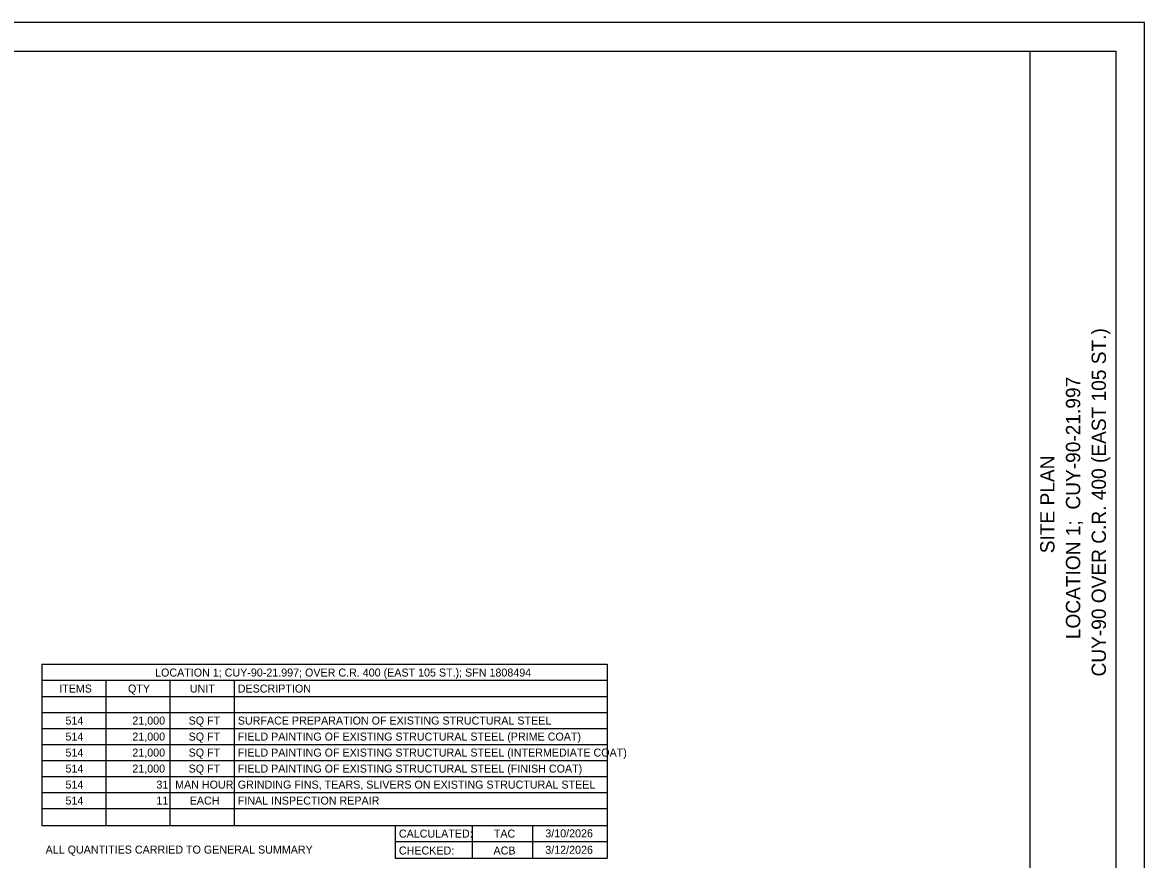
# Model space of a CAD drawing. Extents: x 0 to 34, y 0 to 22.
# Drawn here: x 14.38 to 34, y 7.36 to 22 of the extents above; entities that cross this region are included whole.
import ezdxf

# ---------------------------------------------------------------- set-up
doc = ezdxf.new("R2010")
doc.units = 0
for name, color, linetype in [('SH_Border', 7, 'Continuous'), ('SH_Cut_Line', 7, 'Continuous'), ('SH_Data', 7, 'Continuous'), ('SH_Text', 7, 'Continuous')]:
    doc.layers.add(name, color=color, linetype=linetype)

msp = doc.modelspace()

# ---------------------------------------------------------------- linework, layer by layer
at = {"layer": 'SH_Border'}
msp.add_line((32, 0.5), (32, 21.5), dxfattribs=at)
msp.add_lwpolyline([(1.5, 21.5), (33.5, 21.5), (33.5, 0.5), (1.5, 0.5)], close=True, dxfattribs=at)
at = {"layer": 'SH_Cut_Line'}
msp.add_lwpolyline([(0, 0), (34, 0), (34, 22), (0, 22)], close=True, dxfattribs=at)
at = {"layer": 'SH_Text'}
for p, q in [((14.718, 10.771), (24.601, 10.771)), ((14.718, 10.771), (14.718, 7.954)), ((24.601, 10.771), (24.601, 7.954)), ((14.718, 10.491), (24.601, 10.491)), ((15.838, 10.491), (15.838, 7.954)), ((16.958, 10.491), (16.958, 7.954)), ((18.078, 10.491), (18.078, 7.954)), ((14.718, 10.211), (24.601, 10.211)), ((14.718, 9.931), (24.601, 9.931)), ((14.718, 9.651), (24.601, 9.651)), ((14.718, 9.371), (24.601, 9.371)), ((14.718, 9.091), (24.601, 9.091)), ((14.718, 8.811), (24.601, 8.811)), ((14.718, 8.531), (24.601, 8.531)), ((14.718, 8.251), (24.601, 8.251)), ((14.718, 7.954), (24.601, 7.954)), ((20.895, 7.954), (24.601, 7.954)), ((20.895, 7.954), (20.895, 7.378)), ((22.245, 7.954), (22.245, 7.378)), ((23.3, 7.954), (23.3, 7.378)), ((24.601, 7.954), (24.601, 7.378)), ((20.895, 7.674), (24.601, 7.674)), ((20.895, 7.378), (24.601, 7.378))]:
    msp.add_line(p, q, dxfattribs=at)

# ---------------------------------------------------------------- texts
at = {"layer": 'SH_Data'}
for s, p in [('CUY-90 OVER C.R. 400 (EAST 105 ST.)', (33.325, 10.558)), ('LOCATION 1;  CUY-90-21.997', (32.875, 11.211)), ('SITE PLAN', (32.425, 12.714))]:
    msp.add_text(s, height=0.25, rotation=90, dxfattribs=at).set_placement(p)
at = {"layer": 'SH_Text'}
for s, p in [('LOCATION 1; CUY-90-21.997; OVER C.R. 400 (EAST 105 ST.); SFN 1808494', (16.698, 10.557)), ('ITEMS', (15.021, 10.277)), ('QTY', (16.225, 10.277)), ('UNIT', (17.306, 10.277)), ('DESCRIPTION', (18.144, 10.277)), ('514', (15.131, 9.717)), ('      21,000', (15.988, 9.717)), ('SQ FT', (17.284, 9.717)), ('SURFACE PREPARATION OF EXISTING STRUCTURAL STEEL', (18.144, 9.717)), ('514', (15.131, 9.437)), ('      21,000', (15.988, 9.437)), ('SQ FT', (17.284, 9.437)), ('FIELD PAINTING OF EXISTING STRUCTURAL STEEL (PRIME COAT)', (18.144, 9.437)), ('514', (15.131, 9.157)), ('      21,000', (15.988, 9.157)), ('SQ FT', (17.284, 9.157)), ('FIELD PAINTING OF EXISTING STRUCTURAL STEEL (INTERMEDIATE COAT)', (18.144, 9.157)), ('514', (15.131, 8.877)), ('      21,000', (15.988, 8.877)), ('SQ FT', (17.284, 8.877)), ('FIELD PAINTING OF EXISTING STRUCTURAL STEEL (FINISH COAT)', (18.144, 8.877)), ('514', (15.131, 8.597)), ('              31', (15.993, 8.597)), ('MAN HOUR', (17.048, 8.597)), ('GRINDING FINS, TEARS, SLIVERS ON EXISTING STRUCTURAL STEEL', (18.144, 8.597)), ('514', (15.131, 8.317)), ('              11', (15.993, 8.317)), ('EACH', (17.303, 8.317)), ('FINAL INSPECTION REPAIR', (18.144, 8.317)), ('CALCULATED:', (20.961, 7.74)), ('TAC', (22.621, 7.74)), ('3/10/2026', (23.521, 7.744)), ('ALL QUANTITIES CARRIED TO GENERAL SUMMARY', (14.784, 7.46)), ('CHECKED:', (20.961, 7.444)), ('ACB', (22.615, 7.444)), ('3/12/2026', (23.521, 7.456))]:
    msp.add_text(s, height=0.14, dxfattribs=at).set_placement(p)

doc.saveas('drawing.dxf')
